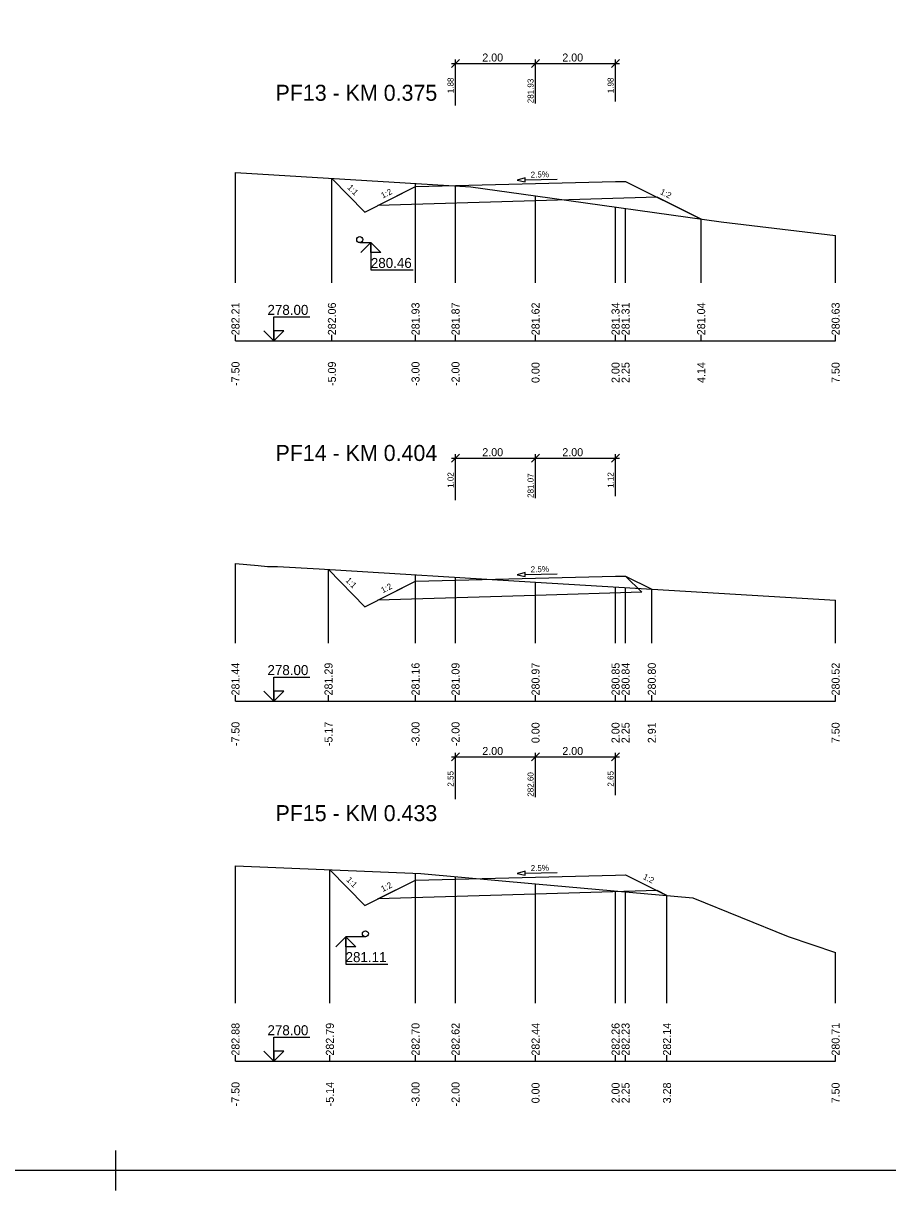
# Model space of a CAD drawing. Extents: x -5 to 1895, y -2 to 602.
# Drawn here: x 817 to 1033, y -2.3 to 289.4 of the extents above; entities that cross this region are included whole.
import ezdxf

# ---------------------------------------------------------------- set-up
doc = ezdxf.new("R2010")
doc.units = 0
for name, color, linetype in [('KOTA', 7, 'Continuous'), ('KOTA_DELKY', 7, 'Continuous'), ('KOTA_DELKY_CONT', 7, 'Continuous'), ('KRIZENI', 7, 'Continuous'), ('NS_TELESO_VOZOVKY', 7, 'Continuous'), ('NS_V_PF', 7, 'Continuous'), ('REZY_PF_PUVODNI', 7, 'Continuous'), ('SESTAVY_REZU_PF', 7, 'Continuous'), ('SKLON', 7, 'Continuous'), ('SVK', 7, 'Continuous')]:
    doc.layers.add(name, color=color, linetype=linetype)

msp = doc.modelspace()

# ---------------------------------------------------------------- linework, layer by layer
for p, q in [((840, 7.67), (840, -2.33)), ((840, 7.67), (840, -2.33)), ((840, 7.67), (840, -2.33)), ((840, 7.67), (840, -2.33)), ((840, 7.67), (840, -2.33)), ((840, 7.67), (840, -2.33)), ((840, 7.67), (840, -2.33)), ((840, 7.67), (840, -2.33)), ((840, 7.67), (840, -2.33)), ((840, 7.67), (840, -2.33)), ((840, 7.67), (840, -2.33)), ((840, 7.67), (840, -2.33)), ((845, 2.67), (835, 2.67)), ((845, 2.67), (835, 2.67)), ((845, 2.67), (835, 2.67)), ((845, 2.67), (835, 2.67)), ((845, 2.67), (835, 2.67)), ((845, 2.67), (835, 2.67)), ((845, 2.67), (835, 2.67)), ((845, 2.67), (835, 2.67)), ((845, 2.67), (835, 2.67)), ((845, 2.67), (835, 2.67)), ((845, 2.67), (835, 2.67)), ((845, 2.67), (835, 2.67))]:
    msp.add_line(p, q)
msp.add_lwpolyline([(0, 596.67), (1890, 596.67), (1890, 2.67), (0, 2.67)], close=True)
at = {"layer": 'KOTA'}
for points in [[(901.05, 234.55), (903.87, 234.55)], [(903.87, 234.55), (901.37, 232.05), (903.87, 234.55), (903.87, 227.73), (914.41, 227.73)], [(903.87, 234.55), (906.37, 232.05), (903.87, 232.05), (903.87, 234.55)], [(903.87, 234.55), (906.37, 232.05), (903.87, 232.05)], [(879.57, 210), (877.07, 212.5), (879.57, 210), (879.57, 216), (888.57, 216)], [(879.57, 210), (882.07, 212.5), (879.57, 212.5), (879.57, 210)], [(879.57, 210), (882.07, 212.5), (879.57, 212.5)], [(879.57, 120), (877.07, 122.5), (879.57, 120), (879.57, 126), (888.57, 126)], [(879.57, 120), (882.07, 122.5), (879.57, 122.5), (879.57, 120)], [(879.57, 120), (882.07, 122.5), (879.57, 122.5)], [(897.56, 61.1), (895.06, 58.6), (897.56, 61.1), (897.56, 54.28), (908.11, 54.28)], [(902.48, 61.1), (897.56, 61.1)], [(897.56, 61.1), (900.06, 58.6), (897.56, 58.6), (897.56, 61.1)], [(897.56, 61.1), (900.06, 58.6), (897.56, 58.6)], [(879.57, 30), (877.07, 32.5), (879.57, 30), (879.57, 36), (888.57, 36)], [(879.57, 30), (882.07, 32.5), (879.57, 32.5), (879.57, 30)], [(879.57, 30), (882.07, 32.5), (879.57, 32.5)]]:
    msp.add_lwpolyline(points, dxfattribs=at)
at = {"layer": 'KOTA_DELKY'}
for points in [[(924, 278.31), (926, 280.31)], [(925, 268.81), (925, 280.31)], [(944, 278.31), (946, 280.31)], [(944, 278.31), (946, 280.31)], [(945, 269.31), (945, 280.31)], [(945, 269.31), (945, 280.31)], [(964, 278.31), (966, 280.31)], [(965, 269.81), (965, 280.31)], [(924, 279.31), (946, 279.31)], [(944, 279.31), (966, 279.31)], [(924, 179.69), (926, 181.69)], [(925, 170.19), (925, 181.69)], [(944, 179.69), (946, 181.69)], [(944, 179.69), (946, 181.69)], [(945, 170.69), (945, 181.69)], [(945, 170.69), (945, 181.69)], [(964, 179.69), (966, 181.69)], [(965, 171.19), (965, 181.69)], [(924, 180.69), (946, 180.69)], [(944, 180.69), (966, 180.69)], [(924, 105.03), (926, 107.03)], [(924, 106.03), (946, 106.03)], [(925, 95.53), (925, 107.03)], [(944, 105.03), (946, 107.03)], [(944, 105.03), (946, 107.03)], [(944, 106.03), (966, 106.03)], [(945, 96.03), (945, 107.03)], [(945, 96.03), (945, 107.03)], [(964, 105.03), (966, 107.03)], [(965, 96.53), (965, 107.03)]]:
    msp.add_lwpolyline(points, dxfattribs=at)
at = {"layer": 'KRIZENI'}
for centre in [(901.05, 235.3), (902.48, 61.85)]:
    msp.add_circle(centre, 0.75, dxfattribs=at)
at = {"layer": 'NS_TELESO_VOZOVKY'}
for points in [[(945, 249.31), (965, 249.81), (967.5, 249.87), (986.4, 240.42), (975.4, 245.92), (945, 245.01), (905.62, 243.83), (915, 248.56), (925, 248.81), (945, 249.31)], [(945, 150.69), (965, 151.19), (967.5, 151.25), (971.57, 147.19), (945, 146.39), (905.62, 145.21), (915, 149.94), (925, 150.19), (945, 150.69)], [(945, 76.03), (965, 76.53), (967.5, 76.6), (977.85, 71.42), (975.4, 72.64), (945, 71.73), (905.62, 70.55), (915, 75.28), (925, 75.53), (945, 76.03)]]:
    msp.add_lwpolyline(points, dxfattribs=at)
at = {"layer": 'NS_V_PF'}
for points in [[(894.1, 250.62), (902.37, 242.19), (915, 248.56), (925, 248.81), (945, 249.31), (965, 249.81), (967.5, 249.87), (986.4, 240.42)], [(893.25, 152.87), (902.37, 143.57), (915, 149.94), (925, 150.19), (945, 150.69), (965, 151.19), (967.5, 151.25), (974.06, 147.98)], [(893.59, 77.86), (902.37, 68.91), (915, 75.28), (925, 75.53), (945, 76.03), (965, 76.53), (967.5, 76.6), (977.85, 71.42)]]:
    msp.add_lwpolyline(points, dxfattribs=at)
at = {"layer": 'REZY_PF_PUVODNI'}
for points in [[(870, 252.09), (928.82, 248.49), (945, 246.22), (945, 246.22), (991.39, 239.72), (1020, 236.31)], [(870, 154.4), (875.71, 153.87), (877.99, 153.67), (878.2, 153.66), (880.51, 153.61), (890.92, 153.01), (945, 149.74), (945, 149.74), (1020, 145.19)], [(870, 78.83), (916.31, 76.94), (945, 74.36), (984.31, 70.84), (1008.15, 61.2), (1020, 57.14)]]:
    msp.add_lwpolyline(points, dxfattribs=at)
at = {"layer": 'SESTAVY_REZU_PF'}
for points in [[(870, 210), (1020, 210)], [(870, 120), (1020, 120)], [(870, 30), (1020, 30)]]:
    msp.add_lwpolyline(points, dxfattribs=at)
at = {"layer": 'SKLON'}
for points in [[(942.39, 250.74), (940.4, 250.19), (942.41, 249.74), (942.39, 250.74)], [(942.4, 250.24), (950.4, 250.44)], [(942.39, 152.13), (940.4, 151.58), (942.41, 151.13), (942.39, 152.13)], [(942.4, 151.63), (950.4, 151.83)], [(942.39, 77.47), (940.4, 76.92), (942.41, 76.47), (942.39, 77.47)], [(942.4, 76.97), (950.4, 77.17)]]:
    msp.add_lwpolyline(points, dxfattribs=at)
for points in [[(942.39, 250.74), (940.4, 250.19), (942.41, 249.74)], [(942.39, 152.13), (940.4, 151.58), (942.41, 151.13)], [(942.39, 77.47), (940.4, 76.92), (942.41, 76.47)]]:
    msp.add_lwpolyline(points, close=True, dxfattribs=at)
at = {"layer": 'SVK'}
for points in [[(870, 224.5), (870, 252.09)], [(894.1, 224.5), (894.1, 250.62)], [(915, 224.5), (915, 249.34)], [(925, 224.5), (925, 248.72)], [(945, 224.5), (945, 246.22)], [(965, 224.5), (965, 243.42)], [(967.5, 224.5), (967.5, 243.07)], [(986.4, 224.5), (986.4, 240.42)], [(1020, 224.5), (1020, 236.31)], [(870, 210), (870, 211.5)], [(894.1, 210), (894.1, 211.5)], [(915, 210), (915, 211.5)], [(925, 210), (925, 211.5)], [(945, 210), (945, 211.5)], [(965, 210), (965, 211.5)], [(967.5, 210), (967.5, 211.5)], [(986.4, 210), (986.4, 211.5)], [(1020, 210), (1020, 211.5)], [(870, 134.5), (870, 154.4)], [(893.25, 134.5), (893.25, 152.87)], [(915, 134.5), (915, 151.55)], [(925, 134.5), (925, 150.95)], [(945, 134.5), (945, 149.74)], [(965, 134.5), (965, 148.53)], [(967.5, 134.5), (967.5, 148.37)], [(974.06, 134.5), (974.06, 147.98)], [(1020, 134.5), (1020, 145.19)], [(870, 120), (870, 121.5)], [(893.25, 120), (893.25, 121.5)], [(915, 120), (915, 121.5)], [(925, 120), (925, 121.5)], [(945, 120), (945, 121.5)], [(965, 120), (965, 121.5)], [(967.5, 120), (967.5, 121.5)], [(974.06, 120), (974.06, 121.5)], [(1020, 120), (1020, 121.5)], [(870, 44.5), (870, 78.83)], [(893.59, 44.5), (893.59, 77.86)], [(915, 44.5), (915, 76.99)], [(925, 44.5), (925, 76.16)], [(945, 44.5), (945, 74.36)], [(965, 44.5), (965, 72.57)], [(967.5, 44.5), (967.5, 72.35)], [(977.85, 44.5), (977.85, 71.42)], [(1020, 44.5), (1020, 57.14)], [(870, 30), (870, 31.5)], [(893.59, 30), (893.59, 31.5)], [(915, 30), (915, 31.5)], [(925, 30), (925, 31.5)], [(945, 30), (945, 31.5)], [(965, 30), (965, 31.5)], [(967.5, 30), (967.5, 31.5)], [(977.85, 30), (977.85, 31.5)], [(1020, 30), (1020, 31.5)]]:
    msp.add_lwpolyline(points, dxfattribs=at)

# ---------------------------------------------------------------- texts
at = {"layer": 'KOTA'}
for s, p in [('280.46', (903.83, 228.23)), ('278.00', (877.99, 216.5)), ('278.00', (877.99, 126.5)), ('281.11', (897.52, 54.78)), ('278.00', (877.99, 36.5))]:
    msp.add_text(s, height=2.5, dxfattribs=at).set_placement(p)
at = {"layer": 'KOTA_DELKY'}
for p in [(931.69, 279.81), (951.69, 279.81), (931.69, 181.19), (951.69, 181.19), (931.69, 106.53), (951.69, 106.53)]:
    msp.add_text('2.00', height=2, dxfattribs=at).set_placement(p)
at = {"layer": 'KOTA_DELKY_CONT'}
for s, p in [('1.88', (924.5, 271.9)), ('281.93', (944.5, 269.39)), ('1.98', (964.5, 271.9)), ('1.02', (924.5, 173.28)), ('281.07', (944.5, 170.77)), ('1.12', (964.5, 173.28)), ('2.55', (924.5, 98.62)), ('282.60', (944.5, 96.11)), ('2.65', (964.5, 98.62))]:
    msp.add_text(s, height=1.5, rotation=90, dxfattribs=at).set_placement(p)
at = {"layer": 'SESTAVY_REZU_PF'}
for s, p in [('PF13 - KM 0.375', (880, 270)), ('PF14 - KM 0.404', (880, 180)), ('PF15 - KM 0.433', (880, 90))]:
    msp.add_text(s, height=4, dxfattribs=at).set_placement(p)
at = {"layer": 'SKLON'}
for s, rotation, p in [('2.5%', 1.4321, (943.8, 250.78)), ('1:1', 314.4213, (897.85, 248.23)), ('1:2', 26.7649, (906.82, 245.56)), ('1:2', 333.4349, (975.99, 246.75)), ('2.5%', 1.4321, (943.8, 152.16)), ('1:1', 314.4213, (897.42, 150.05)), ('1:2', 26.7649, (906.82, 146.94)), ('2.5%', 1.4321, (943.8, 77.5)), ('1:1', 314.4213, (897.59, 75.21)), ('1:2', 333.4349, (971.71, 75.61)), ('1:2', 26.7649, (906.82, 72.28))]:
    msp.add_text(s, height=1.5, rotation=rotation, dxfattribs=at).set_placement(p)
at = {"layer": 'SVK'}
for s, p in [(' 282.21', (871, 210.67)), (' 282.06', (895.1, 210.67)), (' 281.93', (916, 210.67)), (' 281.87', (926, 210.67)), (' 281.62', (946, 210.67)), (' 281.34', (966, 210.67)), (' 281.31', (968.5, 210.67)), (' 281.04', (987.4, 210.67)), (' 280.63', (1021, 210.67)), (' -7.50', (871, 198)), (' -5.09', (895.1, 198)), (' -3.00', (916, 198)), (' -2.00', (926, 198)), ('  0.00', (946, 198)), ('  2.00', (966, 198)), ('  2.25', (968.5, 198)), ('  4.14', (987.4, 198)), ('  7.50', (1021, 198)), (' 281.44', (871, 120.67)), (' 281.29', (894.25, 120.67)), (' 281.16', (916, 120.67)), (' 281.09', (926, 120.67)), (' 280.97', (946, 120.67)), (' 280.85', (966, 120.67)), (' 280.84', (968.5, 120.67)), (' 280.80', (975.06, 120.67)), (' 280.52', (1021, 120.67)), (' -7.50', (871, 108)), (' -5.17', (894.25, 108)), (' -3.00', (916, 108)), (' -2.00', (926, 108)), ('  0.00', (946, 108)), ('  2.00', (966, 108)), ('  2.25', (968.5, 108)), ('  2.91', (975.06, 108)), ('  7.50', (1021, 108)), (' 282.88', (871, 30.67)), (' 282.79', (894.59, 30.67)), (' 282.70', (916, 30.67)), (' 282.62', (926, 30.67)), (' 282.44', (946, 30.67)), (' 282.26', (966, 30.67)), (' 282.23', (968.5, 30.67)), (' 282.14', (978.85, 30.67)), (' 280.71', (1021, 30.67)), (' -7.50', (871, 18)), (' -5.14', (894.59, 18)), (' -3.00', (916, 18)), (' -2.00', (926, 18)), ('  0.00', (946, 18)), ('  2.00', (966, 18)), ('  2.25', (968.5, 18)), ('  3.28', (978.85, 18)), ('  7.50', (1021, 18))]:
    msp.add_text(s, height=2, rotation=90, dxfattribs=at).set_placement(p)

doc.saveas('drawing.dxf')
